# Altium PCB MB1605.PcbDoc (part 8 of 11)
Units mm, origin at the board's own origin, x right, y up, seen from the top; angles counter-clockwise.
Board outline 100 x 79.6 mm, 6 copper layers (Top Layer, Signal Layer 1, Signal Layer 2, Signal Layer 3, Signal Layer 4, Bottom Layer), stack 1.549 mm thick; 644 components, 529 nets, 2853 pads, 1462 vias.
Unrouted connection lines stored in the file: 2.
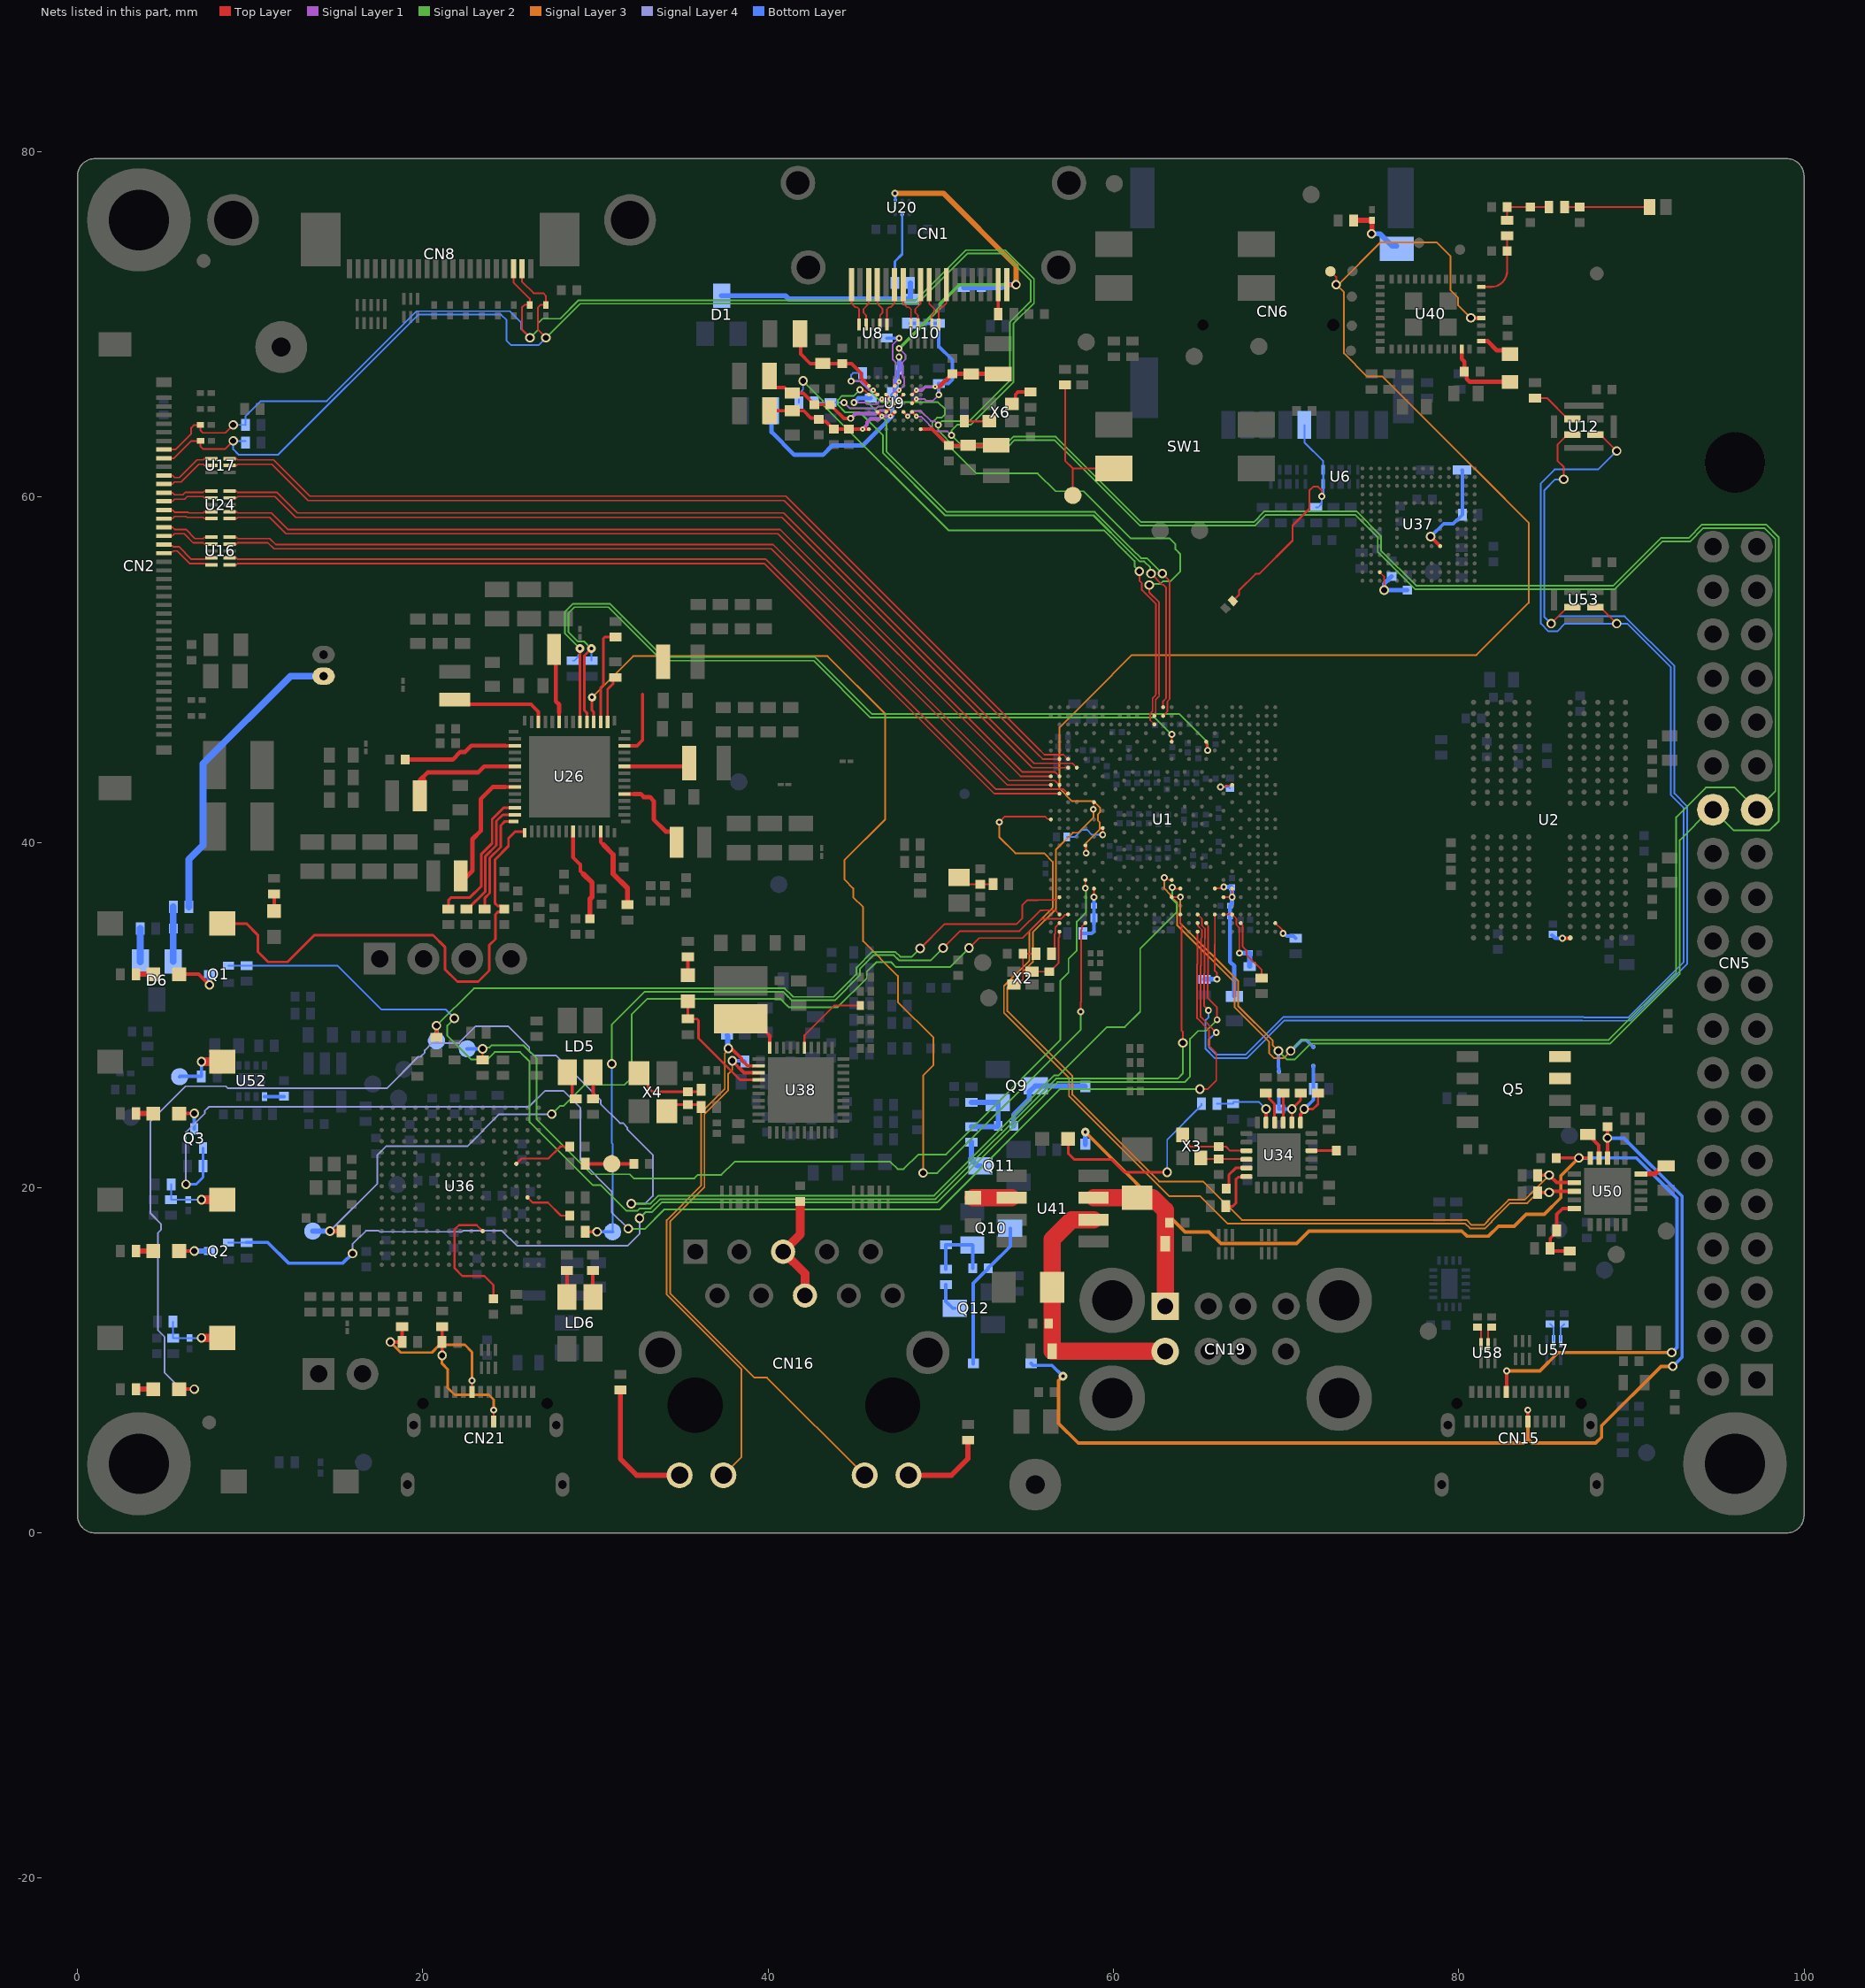
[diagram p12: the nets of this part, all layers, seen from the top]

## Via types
v1: diameter 0.55, hole 0.35, Top Layer to Bottom Layer, 823 vias
v2: diameter 0.4, hole 0.2, Top Layer to Bottom Layer, 235 vias
v3: diameter 0.4, hole 0.2, Top Layer to Bottom Layer, tented both sides, 216 vias
v4: diameter 0.5, hole 0.2, Top Layer to Bottom Layer, 159 vias
v5: diameter 0.25/0.3 (per signal layer), hole 0.1, Top Layer to Signal Layer 1, tented both sides, 29 vias

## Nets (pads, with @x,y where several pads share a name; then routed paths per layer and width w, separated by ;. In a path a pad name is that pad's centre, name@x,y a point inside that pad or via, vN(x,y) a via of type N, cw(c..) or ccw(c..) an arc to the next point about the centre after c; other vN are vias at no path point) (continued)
HDMI.RST: R24.1 U1.C13 | length 35.2
  Top Layer w0.09: U1.C13@62.375,46.825 62.125,47.075 62.125,47.458 62.265,47.598 62.265,48.345 62.45,48.53 62.45,48.575
  Top Layer w0.1: v1(61.5,55.7) 61.5,55.151 61.65,55.001 61.65,54.617 62.45,53.817 62.45,48.575
  Signal Layer 2 w0.1: v1(42.025,66.725) 43.156,65.594 43.156,65.361 50.442,58.075 59.442,58.075 60.716,56.802 61.225,56.292 61.225,55.975 v1(61.5,55.7)
  Bottom Layer w0.1: R24.1@41.784,65.471 41.784,65.978 42.025,66.219 v1(42.025,66.725)
HDMI_I2S2.CK: R16.2 U1.B13 U9.C2 | length 39.2
  Top Layer w0.09: U1.B13@62.375,47.325 62.4,47.35 62.4,47.478 62.445,47.523 62.445,48.271 62.65,48.476 62.65,48.575
  Top Layer w0.1: v1(62.075,54.9) 62.075,54.475 62.65,53.9 62.65,48.575
  Top Layer w0.13: v5(46.086,66.185) U9.C2@46.336,65.935
  Signal Layer 1 w0.13: v2(44.805,66.712) 45.341,66.712 45.846,66.208 46.063,66.208 v5(46.086,66.185)
  Signal Layer 2 w0.1: v2(44.805,66.712) 45.341,66.712 46.564,65.49 49.841,65.49 50.239,65.092 50.239,64.802 50.034,64.597 49.784,64.597 49.507,64.32 49.507,63.915 52.058,61.364 55.615,61.364 56.644,60.335 58.272,60.335 61.009,57.598 63.256,57.598 63.592,57.261 63.592,56.969 63.876,56.685 63.876,55.701 63.296,55.121 62.857,55.121 62.711,54.975 62.15,54.975 v1(62.075,54.9)
  Bottom Layer w0.1: v2(44.805,66.712) 44.805,67.073 44.912,67.181 R16.2@45.474,67.181
HDMI_I2S2.WS: R17.2 U1.B14 U9.D3 | length 34.8
  Top Layer w0.09: U1.B14@62.875,47.325 63.125,47.575 63.125,48.17 63.251,48.297 63.251,48.575
  Top Layer w0.1: v1(62.831,55.574) 63.25,55.155 63.25,48.576 63.251,48.575
  Top Layer w0.13: v5(46.586,65.685) U9.D3@46.836,65.435
  Signal Layer 1 w0.1: v2(44.974,65.479) 45.613,65.479 45.707,65.385 46.225,65.385 46.275,65.435 46.336,65.435 v5(46.586,65.685)
  Signal Layer 2 w0.1: v2(44.974,65.479) 45.776,65.479 46.859,64.396 46.859,62.623 50.342,59.139 58.916,59.139 61.096,56.959 61.592,56.463 61.942,56.463 v1(62.831,55.574)
  Bottom Layer w0.25: v2(44.974,65.479) 45.221,65.726 R17.2@45.942,65.726
HDMI_I2S2_SDO: U1.A14 U9.C1 | length 33.6
  Top Layer w0.09: U1.A14@62.875,47.825 62.875,48.175 63.05,48.35 63.05,48.575
  Top Layer w0.1: v2(45.32,66.217) 45.378,66.16 45.611,66.16 U9.C1@45.836,65.935 ; v1(62.181,55.565) 62.816,54.93 62.873,54.93 63.05,54.753 63.05,48.575
  Signal Layer 2 w0.1: v2(45.32,66.217) 44.964,65.861 44.283,65.861 44.046,65.624 44.046,65.334 44.47,64.91 45.312,64.91 46.659,63.563 46.659,62.54 50.259,58.939 58.847,58.939 60.906,56.88 61.514,56.273 61.782,56.273 62.135,55.92 62.135,55.611 v1(62.181,55.565)
HDMI_RX0_N: CN1.9 U10.4 | length 2.5
  Top Layer w0.09: U10.4@48.672,69.998 48.672,70.528 48.522,70.678 48.522,70.888 48.826,71.191 CN1.9@48.826,72.3
HDMI_RX0_P: CN1.7 U10.5 | length 2.6
  Top Layer w0.09: CN1.7@47.826,72.3 47.826,71.218 48.049,70.994 48.159,70.994 48.272,70.881 U10.5@48.272,69.998
HDMI_RX1_N: CN1.6 U8.1 | length 2.6
  Top Layer w0.09: U8.1@46.879,69.998 46.879,70.881 46.992,70.994 47.102,70.994 47.326,71.218 CN1.6@47.326,72.3
HDMI_RX1_P: CN1.4 U8.2 | length 2.5
  Top Layer w0.09: CN1.4@46.326,72.3 46.326,71.191 46.629,70.888 46.629,70.678 46.479,70.528 U8.2@46.479,69.998
HDMI_RX2_N: CN1.3 U8.4 | length 2.5
  Top Layer w0.09: U8.4@45.672,69.998 45.672,70.528 45.522,70.678 45.522,70.888 45.826,71.191 CN1.3@45.826,72.3
HDMI_RX2_P: CN1.1 U8.5 | length 2.6
  Top Layer w0.09: CN1.1@44.826,72.3 44.826,71.218 45.049,70.994 45.159,70.994 45.272,70.881 U8.5@45.272,69.998
HDMI_RXC_N: CN1.12 U10.1 | length 2.6
  Top Layer w0.09: U10.1@49.879,69.998 49.879,70.881 49.992,70.994 50.102,70.994 50.326,71.218 CN1.12@50.326,72.3
HDMI_RXC_P: CN1.10 U10.2 | length 2.5
  Top Layer w0.09: CN1.10@49.326,72.3 49.326,71.191 49.629,70.888 49.629,70.678 49.479,70.528 U10.2@49.479,69.998
HPD: C177.2 CN1.19 R15.1 U9.C4 U20.C3 | length 25.5
  Top Layer w0.13: U9.C4@47.336,65.935 v5(47.586,66.185)
  Top Layer w0.2: CN1.19@53.826,72.3 v1(54.356,72.3)
  Signal Layer 1 w0.1: v5(47.586,66.185) 47.886,66.485 47.886,66.876 47.786,66.976 47.786,67.811 47.951,67.976 47.951,68.247 v2(47.586,68.612)
  Signal Layer 2 w0.2: v2(47.586,68.612) 47.598,68.612 49.964,70.978 49.964,71.182 51.081,72.3 v1(54.356,72.3)
  Signal Layer 3 w0.3: v2(47.35,77.6) 50.145,77.6 54.356,73.389 v1(54.356,72.3)
  Bottom Layer w0.15: v2(47.35,77.6) 47.357,77.593 47.357,77.176 U20.C3@47.364,77.169
  Bottom Layer w0.3: R15.1@51.33,72.125 C177.2@52.35,72.125 53.548,72.125 53.723,72.3 v1(54.356,72.3)
HSE_IN: C90.2 U1.AG2 X2.1 | length 3.6
  Top Layer w0.1: X2.1@55.284,32.51 56.318,32.51 56.814,33.005 56.814,34.464 56.875,34.525 U1.AG2@56.875,34.825
HSE_OUT: R75.2 U1.AF2 | length 2
  Top Layer w0.09: 56.59,34.075 56.59,34.686 56.625,34.721 56.625,35.075 U1.AF2@56.875,35.325
  Top Layer w0.1: R75.2@56.409,33.546 56.59,33.727 56.59,34.075
I2C1.SCL: R224.1 U1.P1 U50.18 | length 58.1
  Top Layer w0.09: 55.625,41.494 56.038,41.494 56.182,41.35 56.35,41.35 U1.P1@56.375,41.325
  Top Layer w0.1: v2(53.389,41.17) 53.712,41.494 55.625,41.494
  Top Layer w0.2: R224.1@84.568,19.723 v1(85.243,19.723) 85.318,19.798 U50.18@86.688,19.798
  Signal Layer 3 w0.1: v2(53.389,41.17) 53.389,40.295 54.316,39.367 55.982,39.367 56.479,38.87 56.479,36.209 55.134,34.864 55.134,33.152 53.659,31.677 53.659,30.138 57.426,26.372 57.426,25.301 63.214,19.512 65.009,19.512 65.874,18.648 65.885,18.648 66.604,17.929 80.366,17.929 80.655,17.64 81.536,17.64 81.903,18.006 81.903,18.025 82.975,19.098 83.972,19.098 84.597,19.723 v1(85.243,19.723)
I2C1.SDA: R228.1 U1.M6 U50.17 | length 55
  Top Layer w0.09: v3(58.836,41.914) 58.855,41.934 58.855,42.305 U1.M6@58.875,42.325
  Top Layer w0.2: R228.1@84.568,20.723 v1(85.243,20.723) 85.668,20.298 U50.17@86.688,20.298
  Signal Layer 3 w0.1: v3(58.836,41.914) 58.836,41.429 57.964,40.556 57.674,40.556 57.664,40.566 57.651,40.566 56.669,39.583 56.669,36.114 55.334,34.779 55.334,33.069 53.859,31.594 53.859,30.221 57.626,26.454 57.626,25.384 61.522,21.487 62.647,20.362 65.2,20.362 67.433,18.129 80.449,18.129 80.738,17.84 81.454,17.84 81.703,18.089 81.703,18.108 82.892,19.298 83.818,19.298 v1(85.243,20.723)
I2C2.SCL: CN2.7 CN5.28 CN8.20 R32.1 SB1.1 U1.AC15 U9.E6 U13.1 U19.1 | length 202.5
  Top Layer w0.1: CN2.7@5,62.75 5.67,62.75 6.585,63.665 6.585,64.005 6.754,64.175 U13.1@7.117,64.175 7.117,63.859 7.259,63.717 8.554,63.717 v1(9.017,64.18) ; CN8.20@25.25,73.222 25.25,72.438 26.2,71.488 U19.1@26.2,71.126 25.884,71.126 25.742,70.984 25.742,69.688 v1(26.205,69.226) ; U1.AC15@63.375,36.825 63.381,36.831 63.873,36.831 v3(63.879,36.837)
  Top Layer w0.13: U9.E6@48.336,64.935 v5(48.586,64.685)
  Signal Layer 1 w0.1: v5(48.586,64.685) 48.615,64.656 48.855,64.656 49.705,63.807 50.393,63.807 v2(50.625,63.575)
  Signal Layer 2 w0.1: v1(26.205,69.226) 26.675,69.696 26.675,70.079 26.924,70.328 27.95,70.328 29.022,71.4 48.55,71.4 51.45,74.3 53.735,74.3 55.401,72.634 55.401,71.237 54.2,70.036 54.2,66.648 51.752,64.2 50.961,64.2 50.625,63.864 v2(50.625,63.575) 51.119,63.081 53.778,63.081 54.196,63.498 56.665,63.498 61.61,58.553 68.133,58.553 68.754,59.174 74.069,59.174 75.5,57.743 75.5,56.9 77.53,54.87 81.346,54.87 88.954,54.87 91.712,57.628 93.315,57.628 94.093,58.406 97.515,58.406 ; v1(69.555,27.917) 70.058,27.414 70.489,27.414 71.431,28.356 88.778,28.356 92.8,32.377 92.8,40.132 94.558,41.89 CN5.28@94.73,41.89 95.935,40.685 97.996,40.685 98.545,41.234 98.545,57.658 97.798,58.405 97.515,58.405
  Signal Layer 3 w0.1: v3(63.879,36.837) 63.879,35.312 67.225,31.966 67.225,30.523 69.214,28.534 69.214,28.258 v1(69.555,27.917)
  Bottom Layer w0.1: v1(9.017,64.18) 9.72,64.18 R32.1@9.725,64.175 9.725,64.669 10.615,65.559 14.435,65.559 19.641,70.765 25.04,70.765 25.7,70.105 25.7,69.73 v1(26.205,69.226)
  Bottom Layer w0.2: v1(69.555,27.917) 69.555,26.955 69.585,26.924 69.585,26.724 SB1.1@69.587,26.723
I2C2.SDA: CN2.8 CN5.27 CN8.21 R31.1 SB2.1 U1.AA15 U3.1 U9.E5 U39.1 | length 207.1
  Top Layer w0.09: v3(62.95,37.95) 63.009,37.891 63.118,37.891 63.184,37.825 U1.AA15@63.375,37.825
  Top Layer w0.1: CN2.8@5,62.25 5.585,62.25 6.585,63.25 7.117,63.25 7.117,62.934 7.259,62.792 8.554,62.792 v1(9.017,63.255) ; CN8.21@25.75,73.222 25.75,72.464 26.41,71.804 26.979,71.804 27.125,71.658 U39.1@27.125,71.126 26.809,71.126 26.667,70.984 26.667,69.688 v1(27.13,69.226)
  Top Layer w0.13: U9.E5@47.836,64.935 v5(48.086,64.685)
  Signal Layer 1 w0.1: v5(48.086,64.685) 48.386,64.985 48.84,64.985 49.423,64.402 49.63,64.402 v2(49.857,64.175)
  Signal Layer 2 w0.1: v1(27.13,69.226) 29.105,71.2 48.633,71.2 51.533,74.1 53.652,74.1 55.201,72.552 55.201,71.32 54,70.119 54,66.731 51.669,64.4 50.082,64.4 v2(49.857,64.175) 49.857,63.848 50.824,62.881 53.861,62.881 54.279,63.298 56.582,63.298 61.527,58.353 68.215,58.353 68.836,58.974 74,58.974 75.31,57.664 75.31,56.821 77.426,54.705 77.461,54.67 89.037,54.67 91.785,57.418 93.388,57.418 94.175,58.205 97.715,58.205 98.345,57.575 98.345,42.965 CN5.27@97.27,41.89 95.985,43.175 94.315,43.175 92.6,41.46 92.6,32.46 88.695,28.556 70.906,28.556 v1(70.267,27.917)
  Signal Layer 3 w0.1: v3(62.95,37.95) 62.95,37.32 63.3,36.97 63.3,36.895 63.689,36.506 63.689,35.198 67.025,31.862 67.025,30.44 69.014,28.451 69.014,27.785 69.307,27.492 69.842,27.492 v1(70.267,27.917)
  Bottom Layer w0.1: R31.1@9.725,63.25 9.72,63.255 v1(9.017,63.255) 9.017,62.763 9.33,62.45 11.609,62.45 19.724,70.565 24.535,70.565 24.85,70.25 24.85,69.054 25.104,68.801 26.705,68.801 v1(27.13,69.226)
  Bottom Layer w0.2: v1(70.267,27.917) 70.886,28.536 71.191,28.536 SB2.1@71.577,28.15
I2C7.SCL: R261.1 U1.E15 U26.33 | length 46.6
  Top Layer w0.1: U1.E15@63.375,45.825 v3(63.375,46.25)
  Top Layer w0.15: U26.33@29.5,46.97 29.5,47.5 29.35,47.65 29.35,50.812 v4(29.763,51.225)
  Signal Layer 2 w0.1: v4(29.763,51.225) 29.355,51.633 28.975,51.633 28.423,52.185 28.423,53.261 28.785,53.623 30.744,53.623 33.846,50.521 42.637,50.521 45.932,47.227 55.625,47.227 62.398,47.227 v3(63.375,46.25)
  Bottom Layer w0.1: R261.1@29.763,50.521 v4(29.763,51.225)
I2C7.SDA: R260.1 U1.E19 U26.34 | length 49.4
  Top Layer w0.125: U1.E19@65.375,45.825 v3(65.46,45.325)
  Top Layer w0.15: U26.34@29.1,46.97 v4(29.1,51.225)
  Signal Layer 2 w0.1: v4(29.1,51.225) 28.223,52.102 28.223,53.344 28.702,53.823 30.827,53.823 33.9,50.75 42.691,50.75 46.015,47.427 55.625,47.427 63.818,47.427 65.46,45.785 v3(65.46,45.325)
  Bottom Layer w0.1: R260.1@28.689,50.521 28.784,50.521 28.989,50.726 28.989,50.821 29.063,50.896 29.063,51.188 v4(29.1,51.225)
JTCK_SWCLK: R153.2 TP43.1 U1.AA5 | length 53.9
  Top Layer w0.09: v3(58.375,37.35) U1.AA5@58.375,37.825
  Top Layer w0.1: R153.2@23.465,27.407 v1(23.465,28.041)
  Signal Layer 2 w0.1: v1(23.465,28.041) 23.551,28.127 23.869,28.127 23.994,28.252 25.819,28.252 26.59,27.481 26.59,23.959 29.774,20.775 31.975,20.775 32.213,20.537 35.729,20.537 35.929,20.737 37.297,20.737 38.06,21.5 47.074,21.5 47.499,21.075 47.851,21.075 48.701,21.925 50.303,21.925 56.921,28.543 56.921,31.98 57.398,32.456 57.398,33.253 57.875,33.73 57.875,34.075 57.875,35.412 58.415,35.952 58.415,37.31 v3(58.375,37.35)
  Bottom Layer w0.2: TP43.1@22.575,28.041 v1(23.465,28.041)
JTDI: R207.2 TP41.1 U1.AE3 | length 56
  Top Layer w0.09: 55.625,35.353 55.847,35.575 56.979,35.575 57.125,35.721 57.125,35.736 57.188,35.798 57.348,35.798 U1.AE3@57.375,35.825
  Top Layer w0.1: v1(51.631,33.875) 52.214,34.458 54.73,34.458 55.625,35.353
  Top Layer w0.3: v1(14.62,17.482) R207.2@15.265,17.482
  Signal Layer 2 w0.1: v1(27.467,24.257) 27.935,24.725 28.141,24.725 29.366,25.95 31.684,25.95 32.1,26.367 32.1,30.039 33.007,30.945 40.706,30.945 41.106,30.545 41.201,30.45 43.878,30.45 44.032,30.45 45.714,32.133 45.714,32.503 46.273,33.061 47.118,33.061 47.407,32.772 50.528,32.772 v1(51.631,33.875)
  Signal Layer 4 w0.1: v1(14.62,17.482) 17.36,20.222 17.36,21.885 17.875,22.4 22.575,22.4 24.431,24.257 v1(27.467,24.257)
  Bottom Layer w0.3: TP41.1@13.625,17.482 v1(14.62,17.482)
JTDO_SWDO: R129.2 TP13.1 U1.AC2 | length 42
  Top Layer w0.09: 55.625,36.655 56.67,36.655 56.84,36.825 U1.AC2@56.875,36.825
  Top Layer w0.1: v1(48.806,33.855) 50.209,35.258 54.372,35.258 54.727,35.613 54.727,36.37 55.012,36.655 55.625,36.655
  Top Layer w0.2: R129.2@20.79,28.707 v1(20.79,29.382)
  Signal Layer 2 w0.1: v1(20.79,29.382) 22.953,31.545 40.955,31.545 41.355,31.145 41.449,31.05 43.629,31.05 43.783,31.05 45.114,32.381 45.114,32.751 46.024,33.661 47.367,33.661 47.656,33.372 48.323,33.372 v1(48.806,33.855)
  Bottom Layer w0.2: TP13.1@20.79,28.507 v1(20.79,29.382)
JTMS_SWDIO: R209.2 TP40.1 U1.AE2 | length 43.2
  Top Layer w0.09: 55.92,36.07 55.925,36.075 56.625,36.075 U1.AE2@56.875,35.825
  Top Layer w0.1: v1(50.134,33.875) 51.117,34.858 54.564,34.858 55.777,36.07 55.92,36.07
  Top Layer w0.2: R209.2@29.415,17.443 v1(30.09,17.443)
  Signal Layer 2 w0.1: v1(30.94,27.163) 30.94,29.444 32.721,31.225 32.841,31.345 40.872,31.345 40.992,31.225 41.167,31.05 41.272,30.945 41.367,30.85 43.712,30.85 43.866,30.85 45.314,32.299 45.314,32.668 46.107,33.461 47.284,33.461 47.573,33.172 49.431,33.172 v1(50.134,33.875)
  Bottom Layer w0.1: v1(30.94,27.163) 30.94,22.586 30.985,22.541 TP40.1@30.985,17.443
  Bottom Layer w0.2: v1(30.09,17.443) TP40.1@30.985,17.443
LED1: LD7.2 U1.AB16 | length 99.6
  Top Layer w0.1: v3(63.4,37.387) 63.481,37.387 63.544,37.325 U1.AB16@63.875,37.325
  Top Layer w0.2: LD7.2@5.886,8.327 v1(6.763,8.327)
  Signal Layer 2 w0.1: v1(32.075,19.075) 33.195,19.075 33.657,19.537 49.612,19.537 56.587,26.512 56.834,26.512 59.622,29.3 60.659,29.3 61.55,30.191 61.55,33.847 63.655,35.952 63.655,36.465 63.4,36.72 v3(63.4,37.387)
  Signal Layer 4 w0.1: v1(6.763,8.327) 5.999,8.327 5.05,9.276 5.05,11.353 4.65,11.753 4.65,17.367 4.831,17.549 4.831,17.901 4.225,18.507 4.225,23.845 6.253,25.873 8.589,25.873 8.71,25.752 17.91,25.752 19.735,27.577 19.866,27.577 20.115,27.826 20.115,27.957 20.538,28.38 22.096,28.38 23.066,29.35 24.933,29.35 26.165,28.118 26.165,27.906 26.414,27.657 27.713,27.657 30.3,25.07 30.3,24.849 31.411,23.738 31.588,23.738 31.85,23.476 31.85,23.374 33.325,21.899 33.325,19.511 32.889,19.075 v1(32.075,19.075)
LED2: Q3.1 R137.2 U1.AG18 | length 85.1
  Top Layer w0.1: U1.AG18@64.875,34.825 64.875,32.955 64.849,32.929 64.849,29.81 65.531,29.128 65.531,28.224 65.956,27.799 65.956,26.206 65.462,25.712 v1(65.01,25.712)
  Signal Layer 2 w0.1: v1(31.898,17.622) 31.92,17.6 32.853,17.6 33.991,18.737 49.944,18.737 56.919,25.712 v1(65.01,25.712)
  Signal Layer 4 w0.1: v1(6.28,20.191) 6.28,23.21 7.366,24.296 7.366,24.433 7.615,24.682 26.145,24.682 27.075,25.612 28.143,25.612 29.135,24.62 29.135,21.584 30.939,19.78 30.939,18.581 v1(31.898,17.622)
  Bottom Layer w0.15: v1(6.28,20.191) 6.856,20.191 7.263,20.597 R137.2@7.263,21.252 Q3.1@7.263,22.302
LED3: Q2.1 R141.2 U1.AF19 | length 72.4
  Top Layer w0.09: U1.AF19@65.375,35.325 65.375,35.29 65.485,35.18 65.485,34.08 65.48,34.075
  Top Layer w0.091: 65.475,33.994 65.475,34.001 65.48,34.006 65.48,34.075
  Top Layer w0.1: 65.475,33.994 65.475,32.327 65.449,32.301 65.449,30.993 66.003,30.439 v2(66.003,29.72)
  Signal Layer 2 w0.1: v1(32.55,18.225) 32.917,18.592 33.28,18.592 33.825,19.137 49.778,19.137 56.753,26.112 64.125,26.112 64.442,26.429 64.442,28.617 64.901,29.076 65.359,29.076 v2(66.003,29.72)
  Signal Layer 4 w0.1: v1(15.925,16.182) 15.925,16.727 16.705,17.507 17.435,17.507 17.499,17.443 22.281,17.443 22.345,17.507 24.585,17.507 25.447,16.645 31.874,16.645 32.55,17.321 v1(32.55,18.225)
  Bottom Layer w0.1: Q2.1@8.736,16.827 R141.2@9.786,16.827
  Bottom Layer w0.2: R141.2@9.786,16.827 11.004,16.827 12.204,15.627 15.37,15.627 v1(15.925,16.182)
LED4: Q1.1 R143.2 U1.AE16 | length 77.3
  Top Layer w0.09: U1.AE16@63.875,35.825 63.875,35.334 63.945,35.264 63.945,34.647 63.949,34.643 63.949,34.075
  Top Layer w0.1: 63.949,34.075 63.949,30.385 63.945,30.382 63.945,29.105 64.017,29.033 v1(64.017,28.387)
  Signal Layer 2 w0.1: v1(21.828,29.807) 21.415,29.394 21.415,28.806 22.805,27.416 23.724,27.416 24.158,27.85 25.633,27.85 26.187,27.296 26.187,23.797 29.846,20.137 30.315,20.137 31.803,18.65 32.428,18.65 32.57,18.792 33.195,18.792 33.74,19.337 49.695,19.337 56.67,26.312 63.725,26.312 64.017,26.604 v1(64.017,28.387)
  Bottom Layer w0.1: Q1.1@8.736,32.861 R143.2@9.786,32.861 15.049,32.861 17.585,30.325 21.31,30.325 v1(21.828,29.807)
LPO_32: TP17.1 U1.U5 U40.37 | length 77.1
  Top Layer w0.1: U1.U5@58.375,39.825 v3(58.421,39.379) ; TP17.1@72.573,73.072 72.905,72.739 v1(72.905,72.3)
  Top Layer w0.2: v1(80.7,70.38) 80.702,70.378 81.298,70.378 U40.37@81.3,70.375
  Signal Layer 3 w0.1: v3(58.421,39.379) 58.421,39.977 59.208,40.764 59.208,41.154 59.107,41.255 59.107,41.631 59.228,41.753 59.228,42.017 58.865,42.38 57.608,42.38 56.879,43.109 56.879,46.656 58.797,48.575 61.072,50.85 81.03,50.85 84.05,53.87 84.05,58.516 81.346,61.219 80.457,62.109 75.591,66.975 74.696,66.975 73.35,68.321 73.35,71.855 v1(72.905,72.3) 73.026,72.3 75.476,74.75 78.717,74.75 79.525,73.942 79.525,71.975 79.95,71.55 79.95,71.13 v1(80.7,70.38)
LVDS1.CLK_N: U1.K2 U16.10 | length 54
  Top Layer w0.09: U16.10@8.802,57.675 9.197,57.675 9.272,57.6 11.128,57.6 11.478,57.25 40.279,57.25 53.954,43.575 56.604,43.575 56.854,43.325 U1.K2@56.875,43.325
LVDS1.CLK_P: U1.K1 U16.9 | length 53.4
  Top Layer w0.09: U16.9@8.802,57.275 9.197,57.275 9.272,57.35 9.775,57.35 10.9,57.35 11.024,57.35 11.374,57 40.175,57 53.85,43.325 U1.K1@56.375,43.325
LVDS1.CLKcon_N: CN2.16 U16.1 | length 3.1
  Top Layer w0.09: CN2.16@5,58.25 5.495,58.25 5.62,58.125 6.273,58.125 6.798,57.6 7.282,57.6 7.357,57.675 U16.1@7.752,57.675
LVDS1.CLKcon_P: CN2.17 U16.2 | length 3.1
  Top Layer w0.09: CN2.17@5,57.75 5.495,57.75 5.62,57.875 6.17,57.875 6.695,57.35 7.282,57.35 7.357,57.275 U16.2@7.752,57.275
LVDS1.D0_N: U1.G3 U17.6 | length 55.8
  Top Layer w0.09: U17.6@8.802,62.225 9.197,62.225 9.272,62.15 11.351,62.15 13.451,60.05 41.029,60.05 55.625,45.454 56.004,45.075 57.104,45.075 57.354,44.825 U1.G3@57.375,44.825
LVDS1.D0_P: U1.G2 U17.5 | length 55.2
  Top Layer w0.09: U17.5@8.802,61.825 9.197,61.825 9.272,61.9 9.6,61.9 10.925,61.9 11.247,61.9 13.347,59.8 40.925,59.8 55.625,45.1 55.9,44.825 U1.G2@56.875,44.825
LVDS1.D0con_N: CN2.10 U17.1 | length 3.3
  Top Layer w0.09: CN2.10@5,61.25 5.495,61.25 5.62,61.125 5.904,61.125 6.929,62.15 7.282,62.15 7.357,62.225 U17.1@7.752,62.225
LVDS1.D0con_P: CN2.11 U17.2 | length 3.3
  Top Layer w0.09: CN2.11@5,60.75 5.495,60.75 5.62,60.875 6.008,60.875 7.033,61.9 7.282,61.9 7.357,61.825 U17.2@7.752,61.825
LVDS1.D1_N: U1.H4 U24.10 | length 55.7
  Top Layer w0.09: U24.10@8.802,60.35 9.197,60.35 9.272,60.275 11.541,60.275 12.741,59.075 40.904,59.075 55.404,44.575 56.359,44.575 57.625,44.575 U1.H4@57.875,44.325
LVDS1.D1_P: U1.H3 U24.9 | length 55.1
  Top Layer w0.09: U24.9@8.802,59.95 9.197,59.95 9.272,60.025 10.1,60.025 11.2,60.025 11.437,60.025 12.637,58.825 40.8,58.825 55.3,44.325 56.463,44.325 U1.H3@57.375,44.325
LVDS1.D1con_N: CN2.12 U24.1 | length 2.9
  Top Layer w0.09: CN2.12@5,60.25 5.495,60.25 5.62,60.125 6.095,60.125 6.245,60.275 7.282,60.275 7.357,60.35 U24.1@7.752,60.35
LVDS1.D1con_P: CN2.13 U24.2 | length 2.9
  Top Layer w0.09: CN2.13@5,59.75 5.495,59.75 5.62,59.875 6.198,59.875 6.348,60.025 7.282,60.025 7.357,59.95 U24.2@7.752,59.95
LVDS1.D2_N: U1.J2 U24.7 | length 54.4
  Top Layer w0.09: U24.7@8.802,59.15 9.197,59.15 9.272,59.075 11.228,59.075 12.178,58.125 40.679,58.125 54.729,44.075 56.625,44.075 U1.J2@56.875,43.825
LVDS1.D2_P: U1.J1 U24.6 | length 53.8
  Top Layer w0.09: U24.6@8.802,58.75 9.197,58.75 9.272,58.825 9.5,58.825 10.825,58.825 11.124,58.825 12.074,57.875 40.575,57.875 54.625,43.825 U1.J1@56.375,43.825
LVDS1.D2con_N: CN2.14 U24.4 | length 2.9
  Top Layer w0.09: CN2.14@5,59.25 5.495,59.25 5.62,59.125 6.396,59.125 6.446,59.075 7.282,59.075 7.357,59.15 U24.4@7.752,59.15
LVDS1.D2con_P: CN2.15 U24.5 | length 2.9
  Top Layer w0.09: CN2.15@5,58.75 5.495,58.75 5.62,58.875 6.292,58.875 6.342,58.825 7.282,58.825 7.357,58.75 U24.5@7.752,58.75
LVDS1.D3_N: U1.L3 U16.7 | length 54.2
  Top Layer w0.09: U16.7@8.802,56.475 9.197,56.475 9.272,56.4 39.878,56.4 53.203,43.075 57.123,43.075 57.373,42.825 U1.L3@57.375,42.825
LVDS1.D3_P: U1.L2 U16.6 | length 53.6
  Top Layer w0.09: U16.6@8.802,56.075 9.197,56.075 9.272,56.15 9.525,56.15 10.725,56.15 39.774,56.15 53.099,42.825 U1.L2@56.875,42.825
LVDS1.D3con_N: CN2.18 U16.4 | length 3.1
  Top Layer w0.09: CN2.18@5,57.25 5.08,57.17 5.494,57.17 5.539,57.125 5.865,57.125 6.59,56.4 7.325,56.4 7.346,56.421 7.698,56.421 U16.4@7.752,56.475
LVDS1.D3con_P: CN2.19 U16.5 | length 3.1
  Top Layer w0.09: CN2.19@5,56.75 5.078,56.828 5.507,56.828 5.554,56.875 5.761,56.875 6.486,56.15 7.332,56.15 7.352,56.13 7.697,56.13 U16.5@7.752,56.075
MDF.CCK: U1.AE18 U12.3 U53.3 | length 78.8
  Top Layer w0.09: U1.AE18@64.875,35.825 65.125,35.575 65.125,35.183 65.305,35.003 65.305,34.411 65.29,34.396 65.29,34.085 65.28,34.075 65.275,34.07 65.275,34.04
  Top Layer w0.1: 65.275,34.04 65.275,32.41 65.249,32.384 65.249,30.526 v2(65.5,30.275) ; v1(85.35,52.67) 86.15,53.47 86.3,53.62 U53.3@86.575,53.62 ; v1(86.085,61.026) 86.085,61.732 85.732,62.085 85.732,63.052 86.3,63.62 U12.3@86.575,63.62
  Bottom Layer w0.1: v2(65.5,30.275) 65.5,29.85 65.329,29.679 65.329,28.046 65.876,27.499 67.73,27.499 69.911,29.68 87.154,29.68 87.168,29.666 89.934,29.666 93.225,32.957 93.225,42.095 92.493,42.827 92.493,50.22 89.618,53.095 85.775,53.095 v1(85.35,52.67) 84.956,53.064 84.956,60.396 85.586,61.026 v1(86.085,61.026)
MDF.SDI6: U1.AF18 U12.4 U53.4 | length 80.7
  Top Layer w0.09: U1.AF18@64.875,35.325 64.889,35.311 64.889,35.165 65.125,34.929 65.125,34.486 65.075,34.436 65.075,34.075
  Top Layer w0.1: 65.075,34.075 65.075,32.872 65.049,32.846 65.049,29.893 v2(65.956,28.986) ; U53.4@87.925,53.62 88.2,53.62 88.35,53.47 v1(89.15,52.67) ; U12.4@87.925,63.62 88.2,63.62 88.35,63.47 v1(89.15,62.67)
  Bottom Layer w0.1: v2(65.956,28.986) 65.941,28.986 65.531,28.576 65.531,28.127 65.959,27.699 67.647,27.699 69.828,29.88 87.236,29.88 87.251,29.866 89.843,29.866 93.025,33.048 93.025,42.004 92.293,42.736 92.293,50.137 89.76,52.67 86.156,52.67 85.702,52.216 85.203,52.216 84.756,52.663 84.756,60.797 85.556,61.597 88.077,61.597 v1(89.15,62.67)
MP257_WAKEUP: U1.AF5 U26.32 | length 69.6
  Top Layer w0.09: 58.125,34.075 58.125,34.929 58.165,34.969 58.165,35.115 U1.AF5@58.375,35.325
  Top Layer w0.1: v2(58.106,30.195) 58.106,30.747 58.125,30.765 58.125,34.075
  Top Layer w0.15: v4(29.8,48.4) 29.8,47.653 29.9,47.553 U26.32@29.9,46.97
  Signal Layer 2 w0.1: v1(48.975,20.85) 49.794,20.85 58.106,29.163 v2(58.106,30.195)
  Signal Layer 3 w0.1: v4(29.8,48.4) 32.183,50.783 43.444,50.783 46.778,47.449 46.778,41.336 44.425,38.983 44.425,37.841 44.932,37.334 44.932,36.81 45.498,36.244 45.498,34.273 47.515,32.257 47.515,30.743 49.574,28.684 49.574,27.095 48.975,26.496 v1(48.975,20.85)
NetB2_2: B2.2 C219.2 U26.1 | length 29.6
  Top Layer w0.15: B2.2@8.386,35.3 9.775,35.3 10.438,34.637 10.438,33.673 11.036,33.075 12.162,33.075 13.713,34.625 20.59,34.625 21.275,33.94 21.275,32.657 21.995,31.938 23.213,31.938 23.85,32.575 23.85,34.05 24.2,34.4 24.2,35.825 24.347,35.972 24.554,35.972 C219.2@24.727,36.145 24.562,36.31 24.338,36.31 24.187,36.46 24.187,39.008 24.962,39.783 24.962,40.237 25.355,40.63 U26.1@25.9,40.63
NetB3_2: B3.2 R140.1 TP7.1 | length 3.3
  Top Layer w0.5: v1(7.177,27.3) B3.2@8.386,27.3
  Bottom Layer w0.2: TP7.1@5.913,26.425 5.928,26.441 R140.1@7.177,26.441 v1(7.177,27.3)
NetB4_2: B4.2 R126.2 R128.2 TP3.1 U25.1 | length 4.8
  Top Layer w0.5: v1(7.177,19.3) B4.2@8.386,19.3
  Bottom Layer w0.1: R126.2@5.413,20.187 R128.2@5.413,19.3 U25.1@6.413,19.3 v1(7.177,19.3) TP3.1@8.136,19.3
NetB5_2: B5.2 R127.2 R135.2 TP5.1 U27.1 | length 5
  Top Layer w0.5: v1(7.177,11.3) B5.2@8.386,11.3
  Bottom Layer w0.1: R127.2@5.532,12.237 R135.2@5.532,11.287 U27.1@6.493,11.287 7.164,11.287 v1(7.177,11.3) TP5.1@8.386,11.3
NetC1_2: C1.2 U34.21 X3.3 | length 4.2
  Top Layer w0.1: X3.3@64.018,23.065 64.018,23.015 64.393,22.64 64.393,22.44 64.457,22.376 C1.2@66.088,22.376 66.523,22.376 66.76,22.138 U34.21@67.705,22.138
NetC43_2: C43.2 U26.45 | length 6.7
  Top Layer w0.21: 24.775,45.6 U26.45@25.33,45.6
  Top Layer w0.25: C43.2@19.015,44.79 21.731,44.79 22.176,45.235 22.451,45.235 22.816,45.6 24.775,45.6
NetC78_1: C78.1 C101.2 C122.2 L11.1 U9.D4 U9.E3 | length 9.2
  Top Layer w0.2: L11.1@40.077,67.016 40.077,66.666 40.402,66.341 40.95,66.341 41.275,66.016 42.029,66.016 C122.2@42.689,65.356 C101.2@43.614,65.356 ; C101.2@43.589,65.356 C101.2@43.614,65.356 ; v2(44.787,64.56) 44.385,64.56 43.769,65.176 43.769,65.201 C101.2@43.614,65.356 ; U9.E3@46.836,64.935 v5(47.086,65.185) U9.D4@47.336,65.435
  Signal Layer 1 w0.15: 46.266,64.86 46.302,64.86 46.451,65.01 46.877,65.01 47.052,65.185 v5@47.072,65.185
  Signal Layer 1 w0.2: v2(44.787,64.56) 45.07,64.843 46.249,64.843 46.266,64.86 ; v5@47.072,65.185 v5(47.086,65.185)
NetC79_1: C79.1 C102.1 L13.1 U9.B1 | length 6.1
  Top Layer w0.2: L13.1@41.845,69.456 41.875,69.456 41.875,68.295 42.434,67.736 C79.1@43.164,67.736 C102.1@44.3,67.736 44.823,67.736 45.393,67.166 45.393,66.878 U9.B1@45.836,66.435
NetC80_1: C80.1 C106.1 L16.1 U9.B4 | length 15.1
  Top Layer w0.13: U9.B4@47.336,66.435 v5(47.586,66.685)
  Signal Layer 1 w0.1: v2(47.582,68.111) 47.586,68.107 v5(47.586,66.685)
  Bottom Layer w0.25: L16.1@40.2,64.999 40.2,63.762 41.518,62.443 43.177,62.443 43.73,62.996 45.498,62.996 47.195,64.693 C80.1@47.195,65.92 47.39,66.115 47.39,66.337 47.44,66.387 47.44,67.063 47.465,67.088 47.465,67.209 47.595,67.339 47.595,68.098 v2(47.582,68.111)
NetC81_1: C81.1 R64.2 X1.1 | length 2.1
  Top Layer w0.1: X1.1@51.059,37.975 51.459,37.575 C81.1@52.285,37.575 R64.2@53.035,37.575
NetC88_2: C88.2 D6.2 R66.2 | length 3.2
  Bottom Layer w0.4: D6.2@5.542,33.101 C88.2@5.542,35.008 R66.2@5.542,36.26
NetC92_1: C92.1 R75.1 X2.3 | length 2.9
  Top Layer w0.1: X2.3@54.234,31.76 54.461,31.987 54.694,31.987 54.759,32.052 C92.1@54.759,33.546 R75.1@55.509,33.546
NetC95_1: C95.1 D2.1 Q10.3 | length 8.8
  Bottom Layer w0.2: D2.1@51.875,9.8 D2.1@51.888,9.813 51.888,14.466 52.567,15.145 52.592,15.145 52.747,15.3 C95.1@52.747,15.325 52.747,15.35 52.902,15.505 52.927,15.505 54.022,16.6 Q10.3@54.022,17.638
NetC95_2: C95.2 Q10.1 R12.1 R187.2 | length 4.3
  Bottom Layer w0.2: R187.2@50.297,15.275 R12.1@50.297,16.688 Q10.1@51.822,16.688 51.847,16.662 C95.2@51.847,15.325
NetC96_1: C96.1 C107.1 L17.1 U9.G7 | length 4.8
  Top Layer w0.2: U9.G7@48.836,63.935 49.503,63.935 50.446,62.992 L17.1@53.214,62.992
NetC97_1: C97.1 C108.2 L18.1 U9.C6 | length 5.5
  Top Layer w0.13: U9.C6@48.336,65.935 v5(48.586,66.185)
  Top Layer w0.25: v5(49.671,66.385) 49.903,66.385 50.651,67.132 C108.2@50.676,67.132 C97.1@51.769,67.132 L18.1@53.326,67.132
  Signal Layer 1 w0.2: v5(48.586,66.185) 48.9,66.185 49.1,66.385 v5(49.671,66.385)
NetC98_1: C98.1 C113.2 C125.2 C139.2 L19.1 U9.E2 U9.E4 U9.G1 | length 8.9
  Top Layer w0.2: L19.1@40.08,64.999 C98.1@41.4,64.999 42.06,64.999 42.48,64.579 42.863,64.579 43.069,64.373 43.352,64.373 43.635,64.09 C125.2@43.79,63.935 ; C125.2@43.815,63.935 C113.2@44.676,63.935 v5(45.476,63.935) U9.G1@45.836,63.935 ; U9.E2@46.336,64.935 v5(46.586,64.685) ; v5(47.086,64.685) U9.E4@47.336,64.935
  Signal Layer 1 w0.2: v5(45.476,63.935) 45.736,64.195 45.736,64.33 45.917,64.511 45.941,64.535 46.436,64.535 v5(46.586,64.685) v5(47.086,64.685)
NetC100_2: C100.2 U58.6 | length 1.1
  Top Layer w0.1: C100.2@81.087,11.916 81.3,11.703 U58.6@81.3,10.938
NetC114_2: C114.2 U34.23 | length 2.1
  Top Layer w0.15: C114.2@66.523,19.931 66.691,20.099 66.691,20.744 67.085,21.138 U34.23@67.705,21.138
NetC119_2: C119.2 U34.22 X3.1 | length 2.7
  Top Layer w0.1: X3.1@65.068,21.715 65.132,21.651 C119.2@66.088,21.651 67.692,21.651 U34.22@67.705,21.638
NetC127_2: C127.2 U34.10 | length 1.5
  Top Layer w0.15: U34.10@71.47,22.138 72.917,22.138 C127.2@72.919,22.14
NetC130_2: C130.2 C148.2 U37.C2 | length 3.5
  Top Layer w0.09: U37.C2@75.425,55.655 75.675,55.405 v1(75.675,54.605)
  Bottom Layer w0.25: C148.2@76.11,55.405 75.675,54.97 v1(75.675,54.605) C130.2@77.027,54.605
NetC131_2: C131.2 R181.2 TP33.1 | length 2.8
  Top Layer w0.2: R181.2@29.415,21.382 TP33.1@30.94,21.382 C131.2@32.215,21.382
NetC132_2: C132.2 U36.F13 | length 3.5
  Top Layer w0.12: U36.F13@25.415,21.382 25.715,21.682 27.265,21.682 27.965,22.382 C132.2@28.515,22.382
NetC134_2: C134.2 L10.2 U40.31 | length 4.4
  Top Layer w0.25: U40.31@80.175,68.575 80.175,67.996 80.33,67.841 C134.2@80.33,67.262 80.46,67.132 80.46,66.852 80.642,66.67 L10.2@82.98,66.67
NetC145_2: C145.2 U36.J14 | length 2.9
  Top Layer w0.12: U36.J14@26.065,19.432 26.365,19.132 27.24,19.132 27.99,18.382 C145.2@28.515,18.382
NetC150_2: C150.2 C155.2 CN19.T1 U41.7 U44.1 | length 10
  Top Layer w1: U41.7@58.854,19.413 61.366,19.413 C150.2@61.375,19.422 62.265,19.422 63,18.687 63,17.976 U44.1@63,16.76 CN19.T1@63,13.13
NetC151_2: C151.2 C252.2 C260.2 R11.2 U1.AB20 U1.AB22 U1.AC21 | length 8.5
  Top Layer w0.1: U1.AB20@65.875,37.325 65.895,37.345 66.248,37.345 66.314,37.41 v3(66.395,37.41) ; U1.AC21@66.375,36.825 v3(66.875,36.825) U1.AB22@66.875,37.325
  Bottom Layer w0.25: v3(66.395,37.41) 66.846,37.41 C252.2@66.87,37.385 66.87,36.83 v3(66.875,36.825) 66.875,36.449 C151.2@66.75,36.324 66.75,33.083 67,32.833 R11.2@67,31.075
NetC152_2: C152.2 CN16.5 CN16.6 | length 6.4
  Top Layer w0.5: C152.2@41.865,19.209 41.865,17.29 CN16.5@40.865,16.29 42.135,15.02 CN16.6@42.135,13.75
NetC160_2: C160.2 U36.M10 | length 7.6
  Top Layer w0.12: U36.M10@23.465,17.482 23.115,17.832 22.09,17.832 21.84,17.582 21.84,15.332 22.29,14.882 23.565,14.882 24.09,14.357 C160.2@24.09,13.557
NetC167_2: C167.2 R87.2 U40.41 | length 4.1
  Top Layer w0.11: U40.41@81.3,72.175 81.888,72.175 ccw(c81.888,73.087) 82.8,73.087 C167.2@82.8,74.25 R87.2@82.8,75.125
NetC168_2: C168.2 CN15.A5 D5.2 U50.15 | length 63.9
  Top Layer w0.2: CN15.A5@82.75,8.16 82.775,8.185 v2(82.775,9.387) ; C168.2@85.638,21.723 v1(86.963,21.723) U50.15@87.613,21.723
  Signal Layer 3 w0.2: v4(58.375,23.225) 64.16,17.44 65.544,17.44 66.224,16.76 70.6,16.76 71.319,17.479 80.18,17.479 80.469,17.19 81.723,17.19 82.305,17.773 83.206,17.773 83.897,18.464 84.963,18.464 85.918,19.418 85.918,20.678 v1(86.963,21.723) ; v2(82.775,9.387) 84.702,9.387 85.763,10.449 v1(92.336,10.449)
  Bottom Layer w0.2: v1(86.963,21.723) 90.288,21.723 92.638,19.373 92.638,10.75 v1(92.336,10.449)
  Bottom Layer w0.3: D5.2@58.375,22.513 v4(58.375,23.225)
NetC170_2: C170.2 U50.14 | length 1.6
  Top Layer w0.2: C170.2@87.463,23.103 88.113,22.453 U50.14@88.113,21.723
NetC171_2: C171.2 CN15.B5 D2.2 U50.13 | length 63.4
  Top Layer w0.2: CN15.B5@84,6.46 v2(84,7.12) ; U50.13@88.613,21.723 v1(88.613,22.873) C171.2@88.613,23.548
  Signal Layer 3 w0.2: v4(57.075,9.079) 56.82,8.824 56.82,6.344 57.964,5.2 83.755,5.2 84,5.445 ; v2(84,7.12) 84,5.445 ; v1(92.4,9.65) 91.721,9.65 88.273,6.202 88.273,5.548 87.925,5.2 84.245,5.2 84,5.445
  Bottom Layer w0.2: D2.2@55.238,9.813 55.344,9.706 56.448,9.706 v4(57.075,9.079) ; v1(88.613,22.873) 89.563,22.873 92.938,19.498 92.938,10.188 v1(92.4,9.65)
NetC173_2: C173.2 U52.1 | length 1.1
  Bottom Layer w0.2: U52.1@10.836,25.277 C173.2@11.961,25.277
NetC174_2: C174.2 C175.2 R87.1 R88.2 | length 3.2
  Top Layer w0.11: R87.1@82.8,76.025 C175.2@82.8,76.8 R88.2@85.225,76.8
NetC176_2: C176.2 L9.1 R88.1 | length 4.9
  Top Layer w0.11: R88.1@86.125,76.8 C176.2@87,76.8 L9.1@91.05,76.8
NetC208_1: C208.1 U26.8 | length 5.4
  Top Layer w0.21: U26.8@28.7,40.63 28.7,39.134 29.125,38.709 29.125,38.345 29.298,38.172
  Top Layer w0.3: 29.298,38.172 29.8,37.67 29.8,36.843 29.675,36.718 C208.1@29.675,35.705
NetC212_1: C212.1 D5.1 Q9.3 | length 5.7
  Bottom Layer w0.3: C212.1@54.225,23.575 54.225,24.215 55.123,25.113 55.123,25.538 55.473,25.888 58.35,25.888 D5.1@58.375,25.863
NetC212_2: C212.2 Q9.1 R8.1 R162.2 | length 4.5
  Bottom Layer w0.3: R162.2@51.775,23.525 53.275,23.525 C212.2@53.325,23.575 53.325,24.913 Q9.1@53.3,24.938 R8.1@51.775,24.938
NetC222_2: C222.2 R182.1 X4.1 | length 4.3
  Top Layer w0.15: X4.1@32.525,26.625 33.034,26.116 33.034,25.816 33.3,25.55 C222.2@35.35,25.55 36,25.55 R182.1@36.125,25.675
NetC223_2: C223.2 R188.1 X4.3 | length 2.2
  Top Layer w0.15: X4.3@34.125,24.425 34.5,24.8 C223.2@35.35,24.8 36,24.8 R188.1@36.125,24.675
NetC225_2: C225.2 U1.R7 | length 2.8
  Top Layer w0.1: v3(59.375,40.433) U1.R7@59.375,40.825
  Bottom Layer w0.1: C225.2@57.296,40.309 57.764,40.309 58.18,40.726 58.47,40.726 58.763,40.433 v3(59.375,40.433)
NetC226_2: C226.2 C227.2 CN19.B1 U41.6 U51.1 | length 15.9
  Top Layer w1: U41.6@58.854,18.143 57.59,18.143 56.445,16.998 C226.2@56.445,14.225 U51.1@56.445,10.535 CN19.B1@62.975,10.535
NetC235_2: C235.2 C244.2 R267.1 U1.AB6 | length 3.2
  Top Layer w0.09: v3(58.875,36.825) U1.AB6@58.875,37.325
  Bottom Layer w0.2: R267.1@58.223,34.723 58.734,34.723 58.875,34.864 C235.2@58.875,35.625 C244.2@58.875,36.331 v3(58.875,36.825)
NetC251_2: C251.2 R286.2 U1.AE21 U1.AE22 | length 4.3
  Top Layer w0.09: U1.AE21@66.375,35.825 U1.AE22@66.875,35.825 ; U1.AE22@66.902,35.798 67.125,35.575 67.125,35.221 67.295,35.052 67.295,33.593 v2(67.3,33.588)
  Top Layer w0.1: U1.AE22@66.875,35.825 U1.AE22@66.902,35.798
  Bottom Layer w0.3: v2(67.3,33.588) C251.2@67.89,33.588 R286.2@67.89,32.815
NetC265_2: C265.2 U58.5 | length 1.1
  Top Layer w0.1: U58.5@81.7,10.938 81.7,11.711 C265.2@81.906,11.916
NetC266_2: C266.2 U57.6 | length 1.1
  Bottom Layer w0.1: U57.6@85.898,11.123 85.898,11.888 C266.2@86.111,12.101
NetC267_2: C267.2 U57.5 | length 1.1
  Bottom Layer w0.1: C267.2@85.292,12.101 85.498,11.896 U57.5@85.498,11.123
NetCN1_18: CN1.18 R20.2 | length 1.7
  Top Layer w0.2: R20.2@53.326,70.6 CN1.18@53.326,72.3
NetCN6_5: CN6.5 R9.2 R34.1 U6.1 U6.10 | length 15.1
  Top Layer w0.11: R9.2@66.914,53.986 67.275,54.347 67.275,54.59 68.235,55.55 68.45,55.55 70.375,57.475 70.375,58.349 71.354,59.327 71.354,60.379 71.575,60.6 71.847,60.6 72.068,60.379 v2(72.068,60.042)
  Bottom Layer w0.11: CN6.5@71.06,64.175 71.06,63.165 72.152,62.073 72.152,61.584 U6.1@72.154,61.582 U6.10@72.154,60.762 72.154,60.128 v2(72.068,60.042) 72.068,59.711 72.045,59.688 72.045,59.593 71.845,59.393 R34.1@71.75,59.393
NetCN6_10: CN6.10 R40.2 U54.1 | length 3.6
  Top Layer w0.3: R40.2@73.915,76.025 U54.1@74.975,76.025 74.975,75.275 v1(74.95,75.25)
  Bottom Layer w0.3: v1(74.95,75.25) 75.435,75.25 76.135,74.55 CN6.10@76.41,74.55
NetCN12_1: CN12.1 R66.1 | length 17.7
  Bottom Layer w0.4: R66.1@6.442,36.26 6.442,39.009 7.261,39.828 7.261,44.548 12.338,49.625 CN12.1@14.25,49.625
NetCN16_11: CN16.11 R233.1 | length 7.8
  Top Layer w0.3: R233.1@31.44,8.286 31.44,4.285 32.385,3.34 CN16.11@34.87,3.34
NetCN16_12: CN16.12 R319.2 U38.32 | length 31.5
  Top Layer w0.2: v1(37.696,28.065) 37.763,27.998 37.949,27.998 38.461,27.486 38.461,27.389 38.8,27.05 U38.32@39.45,27.05
  Signal Layer 3 w0.1: CN16.12@37.41,3.34 38.461,4.391 38.461,9.474 34.125,13.81 34.125,18.122 36.111,20.108 36.111,24.346 37.49,25.725 37.49,27.781 37.696,27.987 v1(37.696,28.065)
  Bottom Layer w0.3: R319.2@37.625,28.825 37.661,28.789 37.661,28.1 v1(37.696,28.065)
NetCN16_13: CN16.13 R322.2 U38.33 | length 33.2
  Top Layer w0.2: v1(37.925,27.35) 37.925,27.333 38.608,26.65 U38.33@39.45,26.65
  Signal Layer 3 w0.1: v1(37.925,27.35) 37.925,26.829 37.69,26.594 37.69,25.642 36.311,24.263 36.311,20.025 34.325,18.039 34.325,13.893 39.218,9 39.93,9 CN16.13@45.59,3.34
  Bottom Layer w0.2: v1(37.925,27.35) 38.6,27.35 R322.2@38.65,27.3
NetCN16_14: CN16.14 R234.2 | length 4.9
  Top Layer w0.3: CN16.14@48.13,3.34 50.615,3.34 51.575,4.3 R234.2@51.575,5.375
NetCN21_A5: CN21.A5 R217.2 R221.1 | length 9.2
  Top Layer w0.1: CN21.A5@22.85,8.16 v2(22.85,8.82)
  Top Layer w0.2: v1(18.12,11.057) R221.1@18.795,11.057 R217.2@18.795,11.957
  Signal Layer 3 w0.15: v1(18.12,11.057) 18.727,10.45 20.528,10.45 20.969,10.891 22.43,10.891 22.85,10.471 v2(22.85,8.82)
NetCN21_B5: CN21.B5 R218.2 R222.1 | length 7.9
  Top Layer w0.1: CN21.B5@24.1,6.46 v2(24.1,7.12)
  Top Layer w0.2: v1(21.115,10.287) R222.1@21.115,11.057 R218.2@21.115,11.957
  Signal Layer 3 w0.15: v1(21.115,10.287) 21.115,9.803 21.444,9.474 21.444,8.399 21.842,8.001 23.819,8.001 24.1,7.72 v2(24.1,7.12)
NetD1_3: D1.3 R28.1 R29.2 | length 12
  Bottom Layer w0.3: D1.3@37.3,71.658 41.005,71.658 41.198,71.465 R28.1@48.24,71.465 R29.2@48.24,72.403
NetD6_1: D6.1 R67.1 | length 1.9
  Bottom Layer w0.4: D6.1@3.632,33.091 R67.1@3.632,35.008
NetD7_1: D7.1 R248.1 U37.K5 | length 5.7
  Top Layer w0.2: v1(78.375,57.705) U37.K5@78.925,57.155
  Bottom Layer w0.2: v1(78.375,57.705) 79.125,58.455 79.682,58.455 R248.1@80.207,58.98 80.207,61.55 D7.1@80.195,61.563
NetL1_1: L1.1 U26.37 | length 4.2
  Top Layer w0.21: U26.37@27.9,46.97 27.9,47.525
  Top Layer w0.25: L1.1@27.7,51.135 27.7,48.173 27.9,47.973 27.9,47.525
NetL2_1: L2.1 U26.26 | length 4.1
  Top Layer w0.2: U26.26@31.917,45.6 32.4,45.6 32.725,45.925 32.725,48.56 ; L2.1@33.85,49.685 L2.1@33.85,50.2
NetL3_1: L3.1 U26.40 | length 5.9
  Top Layer w0.15: L3.1@21.698,48.162 L3.1@21.85,48.01
  Top Layer w0.21: L3.1@21.85,48.275 22.135,47.99 23.91,47.99 26.265,47.99 26.7,47.555 U26.40@26.7,46.97
NetL4_1: L4.1 U26.23 | length 3.8
  Top Layer w0.15: L4.1@35.36,43.885 L4.1@35.36,44.4
  Top Layer w0.21: U26.23@31.67,44.4 32.225,44.4
  Top Layer w0.25: 32.225,44.4 35,44.4
NetL5_1: L5.1 U26.48 | length 7.2
  Top Layer w0.15: L5.1@19.618,42.448 L5.1@19.87,42.7 ; L5.1@20.09,42.585 L5.1@20.09,43.1
  Top Layer w0.21: 24.775,44.4 U26.48@25.33,44.4
  Top Layer w0.25: 19.825,43.6 20.275,44.05 23.2,44.05 23.55,44.4 24.775,44.4 ; L5.1@20.09,43.1 20.09,43.615
NetL6_1: L6.1 U26.19 | length 4.9
  Top Layer w0.21: U26.19@31.67,42.8 32.225,42.8
  Top Layer w0.25: 32.225,42.8 32.623,42.8 32.798,42.625 33.15,42.625 33.375,42.4 33.375,41.325 34.071,40.629 34.425,40.629 34.43,40.624 L6.1@34.43,40.025
NetL7_1: L7.1 U26.51 | length 7.4
  Top Layer w0.21: 24.775,43.2 U26.51@25.33,43.2
  Top Layer w0.25: L7.1@22.425,38.425 L7.1@22.425,38.669 ; L7.1@22.475,37.95 22.875,38.35 22.875,40.184 23.35,40.659 23.35,42.503 24.047,43.2 24.775,43.2
NetL10_1: L10.1 U40.34 | length 2
  Top Layer w0.25: U40.34@81.3,69.025 81.681,69.025 82.214,68.492 82.759,68.492 L10.1@82.98,68.27
NetL12_2: L12.2 U41.2 | length 2.2
  Top Layer w1: L12.2@51.875,19.413 U41.2@54.104,19.413
NetLD2_1: LD2.1 R158.2 U38.34 | length 7.2
  Top Layer w0.15: LD2.1@35.35,30.795 R158.2@35.35,29.77 35.882,29.77 35.97,29.682 35.97,28.655 38.375,26.25 U38.34@39.45,26.25
NetLD2_2: LD2.2 R151.1 | length 1.1
  Top Layer w0.2: LD2.2@35.35,32.295 R151.1@35.35,33.37
NetLD4_1: LD4.1 R96.1 | length 11.8
  Top Layer w0.15: LD4.1@57.376,22.826 57.376,21.99 57.732,21.635 59.883,21.635 60.629,20.888 v1(63.112,20.888)
  Bottom Layer w0.1: v1(63.112,20.888) 63.112,22.777 65.099,24.764 R96.1@65.099,24.859
NetLD5_1: LD5.1 R131.1 | length 1.5
  Top Layer w0.2: R131.1@29.858,25.15 LD5.1@29.858,26.675
NetLD5_2: LD5.2 R130.2 | length 1.8
  Top Layer w0.2: LD5.2@28.358,26.675 28.65,26.383 28.65,25.305 28.805,25.15 R130.2@28.85,25.15
NetLD6_1: LD6.1 R133.1 | length 1.5
  Top Layer w0.2: LD6.1@28.35,13.669 R133.1@28.35,15.194
NetLD6_2: LD6.2 R132.1 | length 1.5
  Top Layer w0.2: LD6.2@29.85,13.669 R132.1@29.85,15.194
NetLD7_1: LD7.1 R136.2 | length 1
  Top Layer w0.3: R136.2@3.386,8.327 LD7.1@4.386,8.327
NetLD8_1: LD8.1 R138.1 | length 1
  Top Layer w0.3: R138.1@3.386,24.294 LD8.1@4.386,24.294
NetLD8_2: LD8.2 Q3.3 | length 1.8
  Top Layer w0.2: LD8.2@5.886,24.294 v1(6.763,24.294)
  Bottom Layer w0.2: Q3.3@6.763,23.402 v1(6.763,24.294)
NetLD9_1: LD9.1 R142.1 | length 1
  Top Layer w0.3: R142.1@3.386,16.327 LD9.1@4.386,16.327
NetLD9_2: LD9.2 Q2.3 | length 1.7
  Top Layer w0.2: LD9.2@5.886,16.327 v1(6.763,16.327)
  Bottom Layer w0.3: v1(6.763,16.327) Q2.3@7.636,16.327
NetLD11_1: LD11.1 R210.2 | length 1
  Top Layer w0.2: LD11.1@11.386,36.022 R210.2@11.386,37.015
NetLE1_1: LE1.1 U38.30 | length 2.8
  Top Layer w0.2: LE1.1@38.425,29.775 39.175,29.025 39.875,29.025 40.1,28.8 U38.30@40.1,28.1
NetLED1_1: LED1.1 R144.2 | length 1
  Top Layer w0.3: R144.2@3.386,32.361 LED1.1@4.386,32.361
NetLED1_2: LED1.2 Q1.3 | length 2.6
  Top Layer w0.2: LED1.2@5.886,32.361 7.02,32.361 v1(7.636,31.745)
  Bottom Layer w0.3: v1(7.636,31.745) Q1.3@7.636,32.361
NetQ5_7: Q5.7 Q5.8 R225.2 U50.10 | length 1.5
  Top Layer w0.3: U50.10@90.538,20.798 91.358,20.798 R225.2@91.833,21.273
NetQ11_3: Q11.3 R162.1 | length 1.7
  Bottom Layer w0.3: R162.1@51.775,22.625 51.775,21.613 52.125,21.263 Q11.3@52.3,21.263
NetQ12_3: Q12.3 R187.1 | length 1.7
  Bottom Layer w0.2: R187.1@50.297,14.375 50.297,13.413 50.697,13.013 Q12.3@50.822,13.013
NetR1_2: R1.2 U1.K22 | length 1.3
  Top Layer w0.15: v3@66.201,43.202 66.3,43.22 U1.K22@66.875,43.325
  Bottom Layer w0.1: v3(66.2,43.205) 66.67,43.205 R1.2@66.75,43.125
NetR2_1: R2.1 U2.A5 | length 1.1
  Top Layer w0.22: v2@86.009,34.444 U2.A5@86.459,34.444
  Bottom Layer w0.22: R2.1@85.408,34.62 85.583,34.445 v2@86.008,34.445
  other v2: 86.01,34.45
NetR5_2: R5.2 U1.AF27 | length 1.6
  Top Layer w0.1: U1.AF27@69.375,35.325 69.768,34.932 69.768,34.782 v2(69.825,34.725)
  Bottom Layer w0.2: v2(69.825,34.725) 69.879,34.725 70.042,34.562 70.125,34.562 70.439,34.562 R5.2@70.555,34.446
NetR6_1: R6.1 U1.AF23 | length 3.7
  Top Layer w0.09: U1.AF23@67.375,35.325 67.375,35.287 67.485,35.178 67.485,33.966 67.495,33.956
  Top Layer w0.1: 67.495,33.956 67.705,33.746 67.705,33.48 68.584,32.601 R6.1@68.584,32.133
NetR7_1: R7.1 U1.AE20 | length 4.5
  Top Layer w0.09: 65.875,34.075 U1.AE20@65.875,35.825
  Top Layer w0.1: 65.875,34.075 65.875,32.555 65.999,32.431 v2(65.999,32.073)
  Bottom Layer w0.3: R7.1@65.274,32.073 v2(65.999,32.073)
NetR10_2: R10.2 R223.1 R327.2 U50.20 | length 4.5
  Top Layer w0.2: R327.2@86.438,16.325 85.455,16.325 85.3,16.48 85.3,17.06 85.668,17.427 85.668,18.448 86.018,18.798 U50.20@86.688,18.798
NetR18_2: R18.2 U9.C5 | length 5
  Top Layer w0.13: v5(47.586,65.685) U9.C5@47.836,65.935
  Signal Layer 1 w0.1: v5(47.586,65.685) 47.271,66 47.271,66.815 47.386,66.93 47.386,67.798 47.221,67.963 47.221,68.838 v2(47.586,69.203)
  Bottom Layer w0.2: R18.2@46.875,69.203 v2(47.586,69.203)
NetR23_1: R23.1 R28.2 R63.2 U9.D6 | length 8.6
  Top Layer w0.13: U9.D6@48.336,65.435 v5(48.586,65.685)
  Signal Layer 1 w0.1: v5(48.586,65.685) 49.041,65.685 49.141,65.585 49.552,65.585 v2(49.887,65.92)
  Bottom Layer w0.2: R28.2@48.24,70.065 49.874,70.065 R63.2@49.889,70.05 49.889,68.73 50.671,67.948 50.671,66.804 50.441,66.575 R23.1@49.887,66.575 v2(49.887,65.92)
NetR24_2: R24.2 R25.1 U9.C3 | length 5.1
  Top Layer w0.13: U9.C3@46.836,65.935 v5(47.086,65.685)
  Signal Layer 1 w0.1: v2(44.396,65.479) 44.746,65.129 45.66,65.129 45.661,65.13 46.253,65.13 46.358,65.235 46.636,65.235 46.755,65.354 v5(47.086,65.685)
  Bottom Layer w0.1: R24.2@42.684,65.479 R25.1@43.613,65.479 v2(44.396,65.479)
NetR29_1: R29.1 U20.B1 | length 4.1
  Bottom Layer w0.15: R29.1@47.34,72.403 47.34,73.65 47.764,74.074 U20.B1@47.764,76.369
NetR30_2: R30.2 X6.3 | length 1.4
  Top Layer w0.13: R30.2@51.376,64.395 X6.3@52.813,64.395
NetR44_1: R44.1 SW1.4 TP23.1 | length 9
  Top Layer w0.1: R44.1@57.2,66.5 57.2,62.106 57.651,61.655 ; TP23.1@57.651,60.096 57.651,61.655 ; SW1.4@60.025,61.655 57.651,61.655
NetR46_2: R46.2 U26.30 | length 2.8
  Top Layer w0.15: U26.30@30.7,46.97 30.7,48.87 31.032,49.202 31.032,49.43 R46.2@31.15,49.548
NetR52_1: R52.1 U34.16 | length 1.9
  Top Layer w0.15: R52.1@68.82,25.487 68.825,25.487 69.03,25.282 69.03,25.14 69.337,24.833 U34.16@69.337,23.771
NetR57_2: R57.2 U26.12 | length 4.9
  Top Layer w0.21: U26.12@30.3,40.63 30.3,40.016 30.47,39.845
  Top Layer w0.3: 30.47,39.845 31.025,39.291 31.025,38.174 31.85,37.349 R57.2@31.85,36.4
NetR59_2: R59.2 U26.54 | length 8.5
  Top Layer w0.15: R59.2@21.48,36.145 21.48,36.64 21.65,36.81 22.736,36.81 23.375,37.449 23.375,39.298 24.012,39.935 24.012,41.335 24.677,42 U26.54@25.33,42
NetR60_2: R60.2 U26.55 | length 7.1
  Top Layer w0.15: R60.2@22.53,36.145 22.604,36.145 23.625,37.166 23.625,39.194 24.262,39.832 24.262,41.232 24.631,41.6 U26.55@25.33,41.6
NetR61_2: R61.2 U26.56 | length 6.1
  Top Layer w0.15: R61.2@23.58,36.145 23.58,36.76 23.875,37.055 23.875,39.091 24.512,39.728 24.512,40.985 24.727,41.2 U26.56@25.255,41.2
NetR69_2: R69.2 U12.2 | length 2.7
  Top Layer w0.11: R69.2@84.416,65.731 85.116,65.731 86.327,64.52 U12.2@86.575,64.52
NetR76_2: R76.2 X6.1 | length 1.6
  Top Layer w0.2: X6.1@54.113,65.395 54.324,65.606 54.324,65.938 54.471,66.085 R76.2@55.196,66.085
NetR81_2: R81.2 U26.31 | length 5.7
  Top Layer w0.15: U26.31@30.3,46.97 30.3,48.973 30.45,49.123 30.45,51.81 30.538,51.898 R81.2@31.163,51.898
NetR94_1: R94.1 R98.2 SB2.2 U34.13 | length 5.2
  Top Layer w0.15: v1(71.049,24.55) 71.56,24.55 71.85,24.84 R94.1@71.85,25.487
  Top Layer w0.2: U34.13@70.837,23.771 70.837,24.243 71.049,24.455 v1(71.049,24.55)
  Bottom Layer w0.2: v1(71.049,24.55) 71.577,25.077 R98.2@71.577,25.712 SB2.2@71.577,27.05
NetR95_1: R95.1 R99.2 SB1.2 U34.14 | length 3.7
  Top Layer w0.15: U34.14@70.337,23.771 v1(70.337,24.55) 70.844,25.057 R95.1@70.844,25.487
  Bottom Layer w0.2: R99.2@69.587,24.55 SB1.2@69.587,25.623 ; R99.2@69.6,24.55 v1(70.337,24.55)
NetR96_2: R96.2 R102.2 U34.17 | length 3.9
  Top Layer w0.2: U34.17@68.837,23.771 v1(68.837,24.55)
  Bottom Layer w0.1: R96.2@65.999,24.859 R102.2@66.934,24.859 66.934,24.975 68.412,24.975 v1(68.837,24.55)
NetR97_2: R97.2 U34.24 | length 2.7
  Top Layer w0.15: R97.2@66.519,18.927 66.915,18.927 67.108,19.12 67.108,20.498 67.225,20.615 67.681,20.615 U34.24@67.705,20.638
NetR100_2: R100.2 U34.15 | length 1.7
  Top Layer w0.15: U34.15@69.837,23.771 R100.2@69.837,25.487
NetR120_2: R120.2 U38.25 | length 4.7
  Top Layer w0.11: U38.25@42.1,28.1 42.1,28.825 43.819,30.544 R120.2@45.345,30.544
